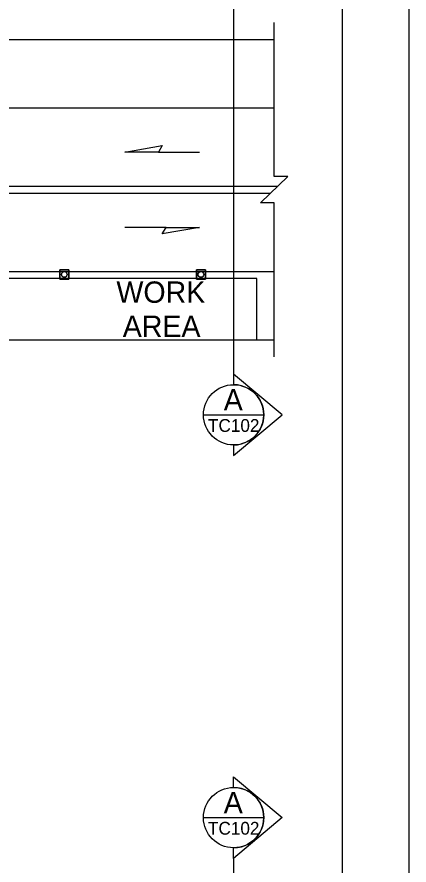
# Model space of a CAD drawing. Extents: x 99999.1 to 100055.7, y 99995 to 100013.2.
# Drawn here: x 100034.226 to 100036.062, y 100004.687 to 100008.662 of the extents above; entities that cross this region are included whole.
import ezdxf

# ---------------------------------------------------------------- set-up
doc = ezdxf.new("R2010")
doc.units = 0
for name, color, linetype in [('RD_MK_LineDblYellowCenter', 7, 'Continuous'), ('RD_MK_LineEdgeWhite', 7, 'Continuous'), ('RD_MK_LineEdgeYellow', 7, 'Continuous'), ('SH_GI_PlotLimits', 7, 'Continuous'), ('SH_GI_SheetBorder', 7, 'Continuous'), ('SH_TI_WZSectionCut', 7, 'Continuous'), ('TR_WZ_TrafficCone', 7, 'Continuous'), ('TR_WZ_WorkAreaLabel', 7, 'Continuous'), ('TR_WZ_WorkZoneDetails', 7, 'Continuous')]:
    doc.layers.add(name, color=color, linetype=linetype)

msp = doc.modelspace()

# ---------------------------------------------------------------- linework, layer by layer
at = {"layer": 'RD_MK_LineDblYellowCenter'}
for p, q in [((100028.2115, 100007.868), (100035.4465, 100007.868)), ((100028.1785, 100007.836), (100035.4135, 100007.836))]:
    msp.add_line(p, q, dxfattribs=at)
at = {"layer": 'RD_MK_LineEdgeWhite'}
msp.add_line((100028.195, 100008.236), (100035.43, 100008.236), dxfattribs=at)
at = {"layer": 'RD_MK_LineEdgeYellow'}
msp.add_line((100033.7951, 100007.468), (100035.43, 100007.468), dxfattribs=at)
at = {"layer": 'SH_GI_PlotLimits'}
msp.add_lwpolyline([(100019.0625, 99999.6875), (100036.0625, 99999.6875), (100036.0625, 100010.6875), (100019.0625, 100010.6875)], close=True, dxfattribs=at)
at = {"layer": 'SH_GI_SheetBorder'}
msp.add_line((100035.75, 100010.375), (100035.75, 100000), dxfattribs=at)
at = {"layer": 'SH_TI_WZSectionCut'}
for p, q in [((100035.2407, 100008.716), (100035.2407, 100006.988)), ((100035.2407, 100006.988), (100035.2407, 100006.9381)), ((100035.4689, 100006.7969), (100035.2407, 100006.988)), ((100035.2407, 100006.6057), (100035.4689, 100006.7969)), ((100035.2407, 100006.6556), (100035.2407, 100006.6057)), ((100035.2407, 100005.0503), (100035.2407, 100005.1002)), ((100035.2407, 100005.1002), (100035.4688, 100004.9091)), ((100035.4688, 100004.9091), (100035.2407, 100004.718)), ((100035.2407, 100004.718), (100035.2407, 100004.7679)), ((100035.2407, 100004.718), (100035.2407, 100002.99))]:
    msp.add_line(p, q, dxfattribs=at)
for points in [[(100035.0995, 100006.7969), (100035.3819, 100006.7969)], [(100035.0995, 100004.9091), (100035.3819, 100004.9091)]]:
    msp.add_lwpolyline(points, dxfattribs=at)
for centre in [(100035.2407, 100006.7969), (100035.2407, 100004.9091)]:
    msp.add_circle(centre, 0.1412, dxfattribs=at)
for centre in [(100035.2407, 100006.7969), (100035.2407, 100004.9091)]:
    msp.add_arc(centre, 0.1412, 269.9978, 90.0022, dxfattribs=at)
at = {"layer": 'TR_WZ_TrafficCone'}
for points in [[(100034.4263, 100007.476), (100034.469, 100007.476), (100034.469, 100007.4333), (100034.4263, 100007.4333), (100034.4263, 100007.476)], [(100034.4263, 100007.4333), (100034.469, 100007.4333), (100034.469, 100007.476), (100034.4263, 100007.476), (100034.4263, 100007.4333)], [(100035.0663, 100007.476), (100035.109, 100007.476), (100035.109, 100007.4333), (100035.0663, 100007.4333), (100035.0663, 100007.476)], [(100035.0663, 100007.4333), (100035.109, 100007.4333), (100035.109, 100007.476), (100035.0663, 100007.476), (100035.0663, 100007.4333)]]:
    msp.add_lwpolyline(points, dxfattribs=at)
for centre in [(100034.4477, 100007.4547), (100035.0877, 100007.4547)]:
    msp.add_circle(centre, 0.0133, dxfattribs=at)
at = {"layer": 'TR_WZ_WorkZoneDetails'}
for p, q in [((100028.195, 100008.556), (100035.43, 100008.556)), ((100034.8886, 100008.0286), (100035.0815, 100008.0286)), ((100034.9242, 100007.6754), (100034.7313, 100007.6754)), ((100033.7951, 100007.148), (100035.43, 100007.148))]:
    msp.add_line(p, q, dxfattribs=at)
msp.add_lwpolyline([(100035.43, 100007.068), (100035.43, 100007.7901), (100035.366, 100007.7901), (100035.494, 100007.9139), (100035.43, 100007.9139), (100035.43, 100008.636)], dxfattribs=at)
for points in [[(100034.7313, 100008.0286), (100034.9064, 100008.0594), (100034.8886, 100008.0286)], [(100035.0815, 100007.6754), (100034.9064, 100007.6446), (100034.9242, 100007.6754)], [(100033.7873, 100007.436), (100033.2263, 100007.052), (100031.7283, 100007.052), (100031.0359, 100006.8182), (100031.0359, 100006.8182), (100031.0359, 100006.8182), (100031.1223, 100006.564), (100031.1223, 100006.564), (100031.1223, 100006.564), (100031.7105, 100006.764), (100033.2341, 100006.764), (100033.5146, 100006.956), (100033.7951, 100007.148), (100035.35, 100007.148), (100035.35, 100007.436)]]:
    msp.add_lwpolyline(points, close=True, dxfattribs=at)

# ---------------------------------------------------------------- texts
at = {"layer": 'SH_TI_WZSectionCut'}
for s, height, rotation, p in [('A', 0.1, 0.01, (100035.1945, 100006.8175)), ('TC102', 0.06, 360, (100035.1209, 100006.7169)), ('A', 0.1, 0.01, (100035.1945, 100004.9297)), ('TC102', 0.06, 360, (100035.1209, 100004.8291))]:
    msp.add_text(s, height=height, rotation=rotation, dxfattribs=at).set_placement(p)
at = {"layer": 'TR_WZ_WorkAreaLabel'}
for s, p in [('WORK', (100034.6919, 100007.322)), ('AREA', (100034.7215, 100007.162))]:
    msp.add_text(s, height=0.1, dxfattribs=at).set_placement(p)

doc.saveas('drawing.dxf')
